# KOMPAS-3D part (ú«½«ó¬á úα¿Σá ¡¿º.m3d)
File: created 24.10.2015 22:02:07, last saved 22.07.2016 18:02:30.
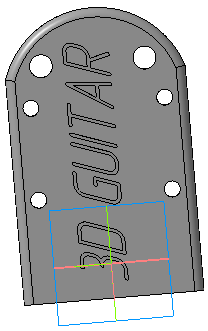
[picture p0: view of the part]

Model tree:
1. Эскиз:1
2. Операция выдавливания:1
     Расстояние 1 = 16
3. Эскиз:11
     Толщина стенки 1 = 2; Толщина стенки 2 = 6; Расстояние 1 = 10; Расстояние 2 = 3
4. Скругление:9
     Радиус = 4
5. Скругление:10
     Радиус = 2
6. Эскиз:12
7. Операция выдавливания:8
     Толщина стенки 1 = 2; Толщина стенки 2 = 6; Расстояние 1 = 15; Расстояние 2 = 3
8. Эскиз:13
9. Операция выдавливания:9
     Толщина стенки 1 = 2; Толщина стенки 2 = 6; Расстояние 1 = 0.5; Расстояние 2 = 3
10. Эскиз:14
11. Вырезать элемент выдавливания:5
     Толщина стенки 2 = 1.5; Расстояние 1 = 22.6
12. Скругление:11
     Радиус = 2
13. Эскиз:15
14. Вырезать элемент выдавливания:6
     Толщина стенки 2 = 1.5; Расстояние 1 = 112.6
15. Эскиз:16
16. Операция выдавливания:10
     Расстояние 1 = 16; Расстояние 2 = 96.2519
17. Скругление:12
     Радиус = 3
18. Эскиз:17
19. Вырезать элемент выдавливания:7
     Расстояние 1 = 40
